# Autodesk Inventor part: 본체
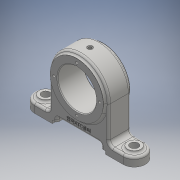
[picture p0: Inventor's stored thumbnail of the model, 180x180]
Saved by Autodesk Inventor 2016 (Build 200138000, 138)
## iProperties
Created: 2019-05
Part Number: 본체
Material: 일반
Document SubType Name: Modeling
Designer: USER
Density: 1 g/cm^3
Appearance: 기본값
Mass: 168.528 g
Surface Area: 318.707 cm^2
Volume: 168.528 cm^3
Author: USER
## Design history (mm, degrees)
sketch "스케치1"
  geometry: L1 (40, 0)-(40, -48); L2 (40, -48)-(60, -48); L3 (60, -48)-(60, -60); L4 (60, -60)-(36, -60); L5 (36, -60)-(36, -56); L6 (36, -56)-(30, -56); L7 (30, -56)-(30, -50); L8 (30, -50)-(20.377, -50); L9 (0, 0)-(0, -81.993); L10 (-40, 0)-(-40, -48); L11 (-40, -48)-(-60, -48); L12 (-60, -48)-(-60, -60); L13 (-36, -60)-(-36, -56); L14 (-36, -56)-(-30, -56); L15 (-30, -56)-(-30, -50); L16 (-30, -50)-(20.377, -50); L17 (-60, -60)-(-36, -60); A1 r 40 centre (0, 0) between (40, 0) and (-40, 0); 1 further point
  constraints: 34 end point, 8 symmetric about line, 7 perpendicular, 2 point on circle, 2 vertical, 1 centre point, 1 coincident, 1 tangent
  dimensions: "d0" = 80 diameter of A1; "d1" = 60 distance from line of L17 point (0, 0); "d2" = 72 distance between parallel lines of L13 L5; "d3" = 60 distance between parallel lines of L15 L7; "d4" = 10 distance between parallel lines of L4 L16; "d5" = 4 distance between parallel lines of L4 L6; "d6" = 12 distance between parallel lines of L4 L2; "d7" = 120 distance between parallel lines of L3 L12
extrude "돌출1" new body sketch "스케치1" stored distance "d9" = 30; taper "d10" = 0 deg
sketch "스케치2"
  geometry: L1 (20, -30)-(20, 0) reference; L2 (-100, -30)-(-100, 0) reference; L3 (-76, 0)-(-100, 0) reference; 3 further points
  constraints: 2 midpoint, 2 vertical alignment, 4 other
extrude "돌출2" join sketch "스케치2" distance "d11" = 12; taper "d12" = 0 deg
sketch "스케치3"
  geometry: C1 r 9 at (20, 15); C2 r 9 at (-100, 15); A1 r 15 centre (20, 15) between (20, 0) and (20, 30) reference; A2 r 15 centre (-100, 15) between (-100, 30) and (-100, 0) reference; 1 further point
  constraints: 2 centre point, 2 coincident
  dimensions: "d13" = 18 diameter of C1; "d14" = 18 diameter of C2
extrude "돌출3" join sketch "스케치3" distance "d15" = 3; taper "d16" = 0 deg
sketch "스케치4"
  geometry: C1 r 9 at (0, 0) reference; C2 r 5.5 at (0, 0); 1 further point
  constraints: 1 centre point, 1 coincident
  dimensions: "d17" = 11 diameter of C2
extrude "돌출4" cut sketch "스케치4" stored distance "d18" = 3; taper "d19" = 0 deg
sketch "스케치5"
  geometry: C1 r 36 at (0, 0); 1 further point
  constraints: 1 centre point, 1 coincident
  dimensions: "d20" = 72 diameter of C1
extrude "돌출5" join sketch "스케치5" distance "d21" = 3; taper "d22" = 0 deg
sketch "스케치6"
  geometry: C1 r 26 at (0, 0); 1 further point
  constraints: 1 centre point, 1 coincident
  dimensions: "d23" = 52 diameter of C1
extrude "돌출6" cut sketch "스케치6" stored distance "d24" = 3; taper "d25" = 0 deg
node "작업 평면1"
sketch "스케치8"
  geometry: 2 further points
  constraints: 1 coincident
hole "구멍1" sketch "스케치8" at (0, 0) diameter "d30" = 4.917; stored, may be unused: countersink angle "d34" = 90 deg, drill point angle "d36" = 118 deg; dims "d31" = 8, "d32" = 7, "d33" = 1, "d35" = 10
sketch "스케치9"
  geometry: C1 r 1 at (0, 0); 1 further point
  constraints: 1 centre point, 1 coincident
  dimensions: "d37" = 2 diameter of C1
extrude "돌출8" cut sketch "스케치9" stored distance "d38" = 3; taper "d39" = 0 deg; dims "d0" = 80, "d1" = 60, "d2" = 72, "d3" = 60, "d4" = 10, "d5" = 4, "d6" = 12, "d7" = 120
sketch "스케치10"
  geometry: L1 (0, 0)-(0, 26); C1 r 1.5 at (0, 26); 1 further point
  constraints: 2 end point, 1 centre point, 1 coincident, 1 vertical, 1 vertical alignment, 1 other
  dimensions: "d40" = 3 diameter of C1
extrude "돌출9" cut sketch "스케치10" stored distance "d41" = 3; taper "d42" = 0 deg
sketch "스케치11"
  geometry: L1 (0, 0)-(0, 31); 1 further point
  constraints: 2 end point, 1 coincident, 1 vertical
  dimensions: "d43" = 31 distance of L1.start L1.end
hole "구멍2" sketch "스케치11" at (0, 31) diameter "d44" = 3.242; stored, may be unused: countersink angle "d48" = 90 deg, drill point angle "d50" = 118 deg; dims "d45" = 6, "d46" = 7, "d47" = 1, "d49" = 8
fillet "모깎기1" dims "d54" = 6
fillet "모깎기2" dims "d55" = 3
chamfer "모따기1" distance "d56" = 1; stored, may be unused: second distance "d57" = 2, angle "d58" = 45 deg
sketch "스케치12"
  geometry: L1 (0, 0)-(0, -50); L2 (27, -50)-(-27, -50) reference; 1 further point
  constraints: 2 end point, 1 midpoint, 1 point on line, 1 other
  dimensions: "d59" = 7 distance from line of point (0, -43) L2
feature "엠보싱1" sketch "스케치12" dims "d0" = 80, "d1" = 60, "d2" = 72, "d3" = 60, "d4" = 10, "d5" = 4, "d6" = 12, "d7" = 120, "d60" = 0.5, "d61" = 0
node "솔리드1"
mirror "대칭1"
mirror "대칭2"
pattern_circular "원형 패턴1" dims angle "d52" = 360 deg
mirror "대칭3"
